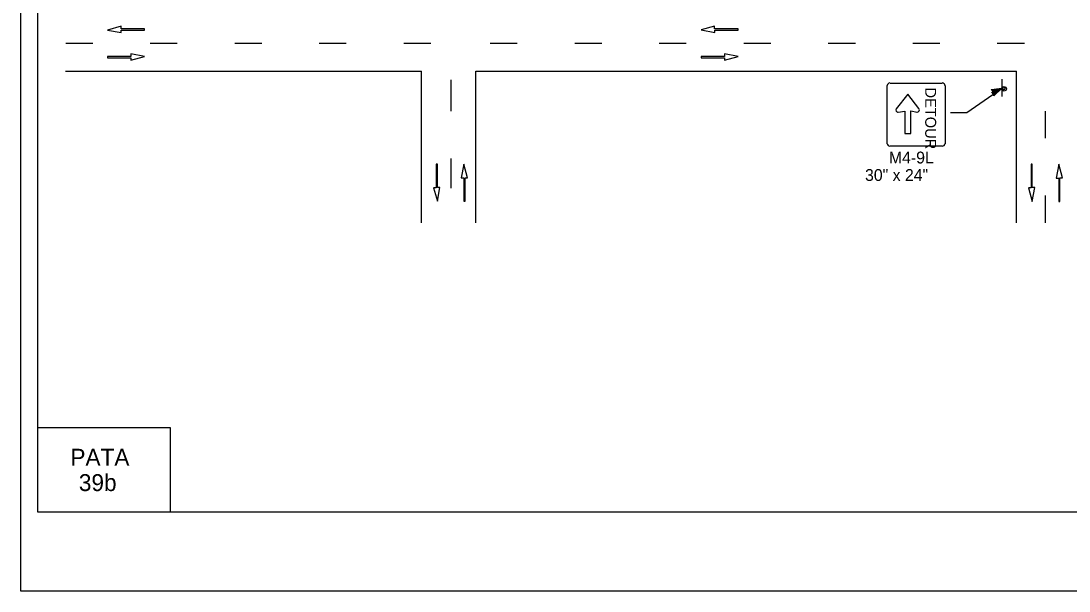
# Model space of a CAD drawing. Extents: x -14145 to -13521, y 30244 to 30661.
# Drawn here: x -13892.17 to -13873.57, y 30262.81 to 30272.92 of the extents above; entities that cross this region are included whole.
import ezdxf

# ---------------------------------------------------------------- set-up
doc = ezdxf.new("R2010")
doc.units = 0
for name, color, linetype in [('1', 7, 'Continuous'), ('10', 7, 'Continuous'), ('2', 7, 'Continuous'), ('4', 7, 'Continuous'), ('61', 7, 'Continuous')]:
    doc.layers.add(name, color=color, linetype=linetype)

msp = doc.modelspace()

# ---------------------------------------------------------------- linework, layer by layer
at = {"layer": '1'}
for p, q in [((-13890.397, 30272.825), (-13890.638, 30272.759)), ((-13890.638, 30272.759), (-13890.395, 30272.713)), ((-13890.397, 30272.78), (-13890.397, 30272.825)), ((-13889.981, 30272.78), (-13890.397, 30272.78)), ((-13890.395, 30272.713), (-13890.395, 30272.758)), ((-13890.395, 30272.758), (-13889.981, 30272.758)), ((-13889.981, 30272.758), (-13889.981, 30272.78)), ((-13879.862, 30272.826), (-13880.103, 30272.76)), ((-13880.103, 30272.76), (-13879.859, 30272.714)), ((-13879.862, 30272.781), (-13879.862, 30272.826)), ((-13879.446, 30272.781), (-13879.862, 30272.781)), ((-13879.859, 30272.714), (-13879.859, 30272.759)), ((-13879.859, 30272.759), (-13879.446, 30272.759)), ((-13879.446, 30272.759), (-13879.446, 30272.781)), ((-13890.9, 30272.522), (-13891.38, 30272.522)), ((-13889.4, 30272.522), (-13889.88, 30272.522)), ((-13887.9, 30272.522), (-13888.38, 30272.522)), ((-13886.4, 30272.522), (-13886.88, 30272.522)), ((-13884.9, 30272.522), (-13885.38, 30272.522)), ((-13883.365, 30272.523), (-13883.845, 30272.523)), ((-13881.865, 30272.523), (-13882.345, 30272.523)), ((-13880.365, 30272.523), (-13880.845, 30272.523)), ((-13878.865, 30272.523), (-13879.345, 30272.523)), ((-13877.365, 30272.523), (-13877.845, 30272.523)), ((-13875.865, 30272.523), (-13876.345, 30272.523)), ((-13874.365, 30272.523), (-13874.845, 30272.523)), ((-13890.225, 30272.289), (-13890.638, 30272.289)), ((-13890.638, 30272.289), (-13890.638, 30272.267)), ((-13890.638, 30272.267), (-13890.222, 30272.267)), ((-13889.981, 30272.288), (-13890.225, 30272.335)), ((-13890.225, 30272.335), (-13890.225, 30272.289)), ((-13890.222, 30272.222), (-13889.981, 30272.288)), ((-13890.222, 30272.267), (-13890.222, 30272.222)), ((-13879.689, 30272.29), (-13880.103, 30272.29)), ((-13880.103, 30272.29), (-13880.103, 30272.268)), ((-13880.103, 30272.268), (-13879.687, 30272.268)), ((-13879.446, 30272.289), (-13879.689, 30272.336)), ((-13879.689, 30272.336), (-13879.689, 30272.29)), ((-13879.687, 30272.223), (-13879.446, 30272.289)), ((-13879.687, 30272.268), (-13879.687, 30272.223)), ((-13891.381, 30272.03), (-13885.062, 30272.03)), ((-13885.062, 30269.341), (-13885.062, 30272.03)), ((-13884.101, 30269.341), (-13884.101, 30272.031)), ((-13884.101, 30272.031), (-13874.504, 30272.031)), ((-13874.504, 30269.341), (-13874.504, 30272.031)), ((-13884.547, 30271.873), (-13884.547, 30271.318)), ((-13876.749, 30271.819), (-13875.823, 30271.819)), ((-13874.765, 30271.889), (-13874.765, 30271.577)), ((-13874.765, 30271.889), (-13874.765, 30271.577)), ((-13874.765, 30271.889), (-13874.765, 30271.577)), ((-13874.765, 30271.889), (-13874.765, 30271.577)), ((-13874.765, 30271.889), (-13874.765, 30271.577)), ((-13874.765, 30271.889), (-13874.765, 30271.577)), ((-13876.798, 30270.743), (-13876.798, 30271.776)), ((-13876.436, 30271.62), (-13876.639, 30271.363)), ((-13876.236, 30271.366), (-13876.436, 30271.62)), ((-13875.773, 30271.776), (-13875.773, 30270.743)), ((-13875.386, 30271.298), (-13874.771, 30271.722)), ((-13876.603, 30271.302), (-13876.489, 30271.322)), ((-13876.489, 30271.322), (-13876.489, 30270.922)), ((-13876.382, 30270.922), (-13876.382, 30271.323)), ((-13876.382, 30271.323), (-13876.27, 30271.304)), ((-13875.674, 30271.298), (-13875.387, 30271.298)), ((-13873.989, 30270.841), (-13873.989, 30271.321)), ((-13876.489, 30270.922), (-13876.382, 30270.922)), ((-13875.823, 30270.7), (-13876.749, 30270.7)), ((-13884.782, 30270.378), (-13884.804, 30270.378)), ((-13884.804, 30270.378), (-13884.804, 30269.962)), ((-13884.782, 30269.964), (-13884.782, 30270.378)), ((-13884.547, 30270.48), (-13884.547, 30269.956)), ((-13884.312, 30270.378), (-13884.358, 30270.135)), ((-13884.246, 30270.137), (-13884.312, 30270.378)), ((-13874.224, 30270.377), (-13874.246, 30270.377)), ((-13874.246, 30270.377), (-13874.246, 30269.961)), ((-13874.224, 30269.963), (-13874.224, 30270.377)), ((-13873.755, 30270.377), (-13873.801, 30270.134)), ((-13873.688, 30270.136), (-13873.755, 30270.377)), ((-13884.358, 30270.135), (-13884.313, 30270.135)), ((-13884.313, 30270.135), (-13884.313, 30269.721)), ((-13884.291, 30269.721), (-13884.291, 30270.137)), ((-13884.291, 30270.137), (-13884.246, 30270.137)), ((-13873.801, 30270.134), (-13873.756, 30270.134)), ((-13873.756, 30270.134), (-13873.756, 30269.72)), ((-13873.733, 30269.72), (-13873.733, 30270.136)), ((-13873.733, 30270.136), (-13873.688, 30270.136)), ((-13884.804, 30269.962), (-13884.849, 30269.962)), ((-13884.849, 30269.962), (-13884.783, 30269.721)), ((-13884.783, 30269.721), (-13884.737, 30269.964)), ((-13884.737, 30269.964), (-13884.782, 30269.964)), ((-13874.246, 30269.961), (-13874.291, 30269.961)), ((-13874.291, 30269.961), (-13874.225, 30269.72)), ((-13874.225, 30269.72), (-13874.179, 30269.963)), ((-13874.179, 30269.963), (-13874.224, 30269.963)), ((-13873.989, 30269.341), (-13873.989, 30269.821)), ((-13884.313, 30269.721), (-13884.291, 30269.721)), ((-13873.756, 30269.72), (-13873.733, 30269.72))]:
    msp.add_line(p, q, dxfattribs=at)
for points in [[(-13874.951, 30271.698), (-13874.939, 30271.686), (-13874.771, 30271.722), (-13874.951, 30271.698), (-13874.957, 30271.704), (-13874.771, 30271.722), (-13874.933, 30271.668), (-13874.939, 30271.656), (-13874.771, 30271.722), (-13874.945, 30271.644), (-13874.939, 30271.656)], [(-13874.951, 30271.698), (-13874.939, 30271.686), (-13874.771, 30271.722), (-13874.951, 30271.698), (-13874.957, 30271.704), (-13874.771, 30271.722), (-13874.933, 30271.668), (-13874.939, 30271.656), (-13874.771, 30271.722), (-13874.945, 30271.644), (-13874.939, 30271.656)], [(-13874.932, 30271.637), (-13874.916, 30271.63), (-13874.771, 30271.722), (-13874.932, 30271.637), (-13874.939, 30271.641), (-13874.771, 30271.722), (-13874.904, 30271.615), (-13874.906, 30271.602), (-13874.771, 30271.722), (-13874.907, 30271.589), (-13874.906, 30271.602)]]:
    msp.add_lwpolyline(points, dxfattribs=at)
msp.add_circle((-13874.725, 30271.716), 0.0408, dxfattribs=at)
msp.add_circle((-13874.725, 30271.716), 0.0408, dxfattribs=at)
msp.add_circle((-13874.725, 30271.716), 0.0408, dxfattribs=at)
for centre, radius, start, end in [((-13874.73, 30271.724), 0.0214, 189.521, 184.2501), ((-13874.73, 30271.724), 0.0214, 189.521, 184.2501), ((-13874.73, 30271.724), 0.0214, 189.521, 184.2501), ((-13876.61, 30271.34), 0.038, 137.8458, 281.7524), ((-13876.267, 30271.342), 0.038, 259.4753, 40.1409)]:
    msp.add_arc(centre, radius, start, end, dxfattribs=at)
for centre, major_axis, start_param, end_param in [((-13876.75, 30271.777), (-0.0492, 0), 4.712389, 6.283185), ((-13875.824, 30271.777), (-0.0492, 0), 3.141593, 4.712389), ((-13876.75, 30270.743), (0.0492, 0), 3.141593, 4.712389), ((-13875.824, 30270.743), (0.0492, 0), 4.712389, 6.283185)]:
    msp.add_ellipse(centre, major_axis=major_axis, ratio=0.866667, start_param=start_param, end_param=end_param, dxfattribs=at)
at = {"layer": '10'}
for p, q in [((-13891.874, 30264.207), (-13891.874, 30286.777)), ((-13891.874, 30265.707), (-13889.524, 30265.707)), ((-13889.524, 30265.707), (-13889.524, 30264.207)), ((-13860.422, 30264.207), (-13891.874, 30264.207))]:
    msp.add_line(p, q, dxfattribs=at)
at = {"layer": '61'}
msp.add_lwpolyline([(-13892.174, 30288.307), (-13859.174, 30288.307), (-13859.174, 30262.807), (-13892.174, 30262.807)], close=True, dxfattribs=at)

# ---------------------------------------------------------------- texts
at = {"layer": '1'}
msp.add_text('DETOUR', height=0.1941, rotation=270, dxfattribs=at).set_placement((-13876.125, 30271.74))
at = {"layer": '2'}
for s, p in [('M4-9L', (-13876.769, 30270.392)), ('30" x 24"', (-13877.193, 30270.082))]:
    msp.add_text(s, height=0.21, dxfattribs=at).set_placement(p)
at = {"layer": '4'}
for s, p in [('PATA', (-13891.296, 30265.03)), ('39b', (-13891.146, 30264.58))]:
    msp.add_text(s, height=0.3, dxfattribs=at).set_placement(p)

doc.saveas('drawing.dxf')
